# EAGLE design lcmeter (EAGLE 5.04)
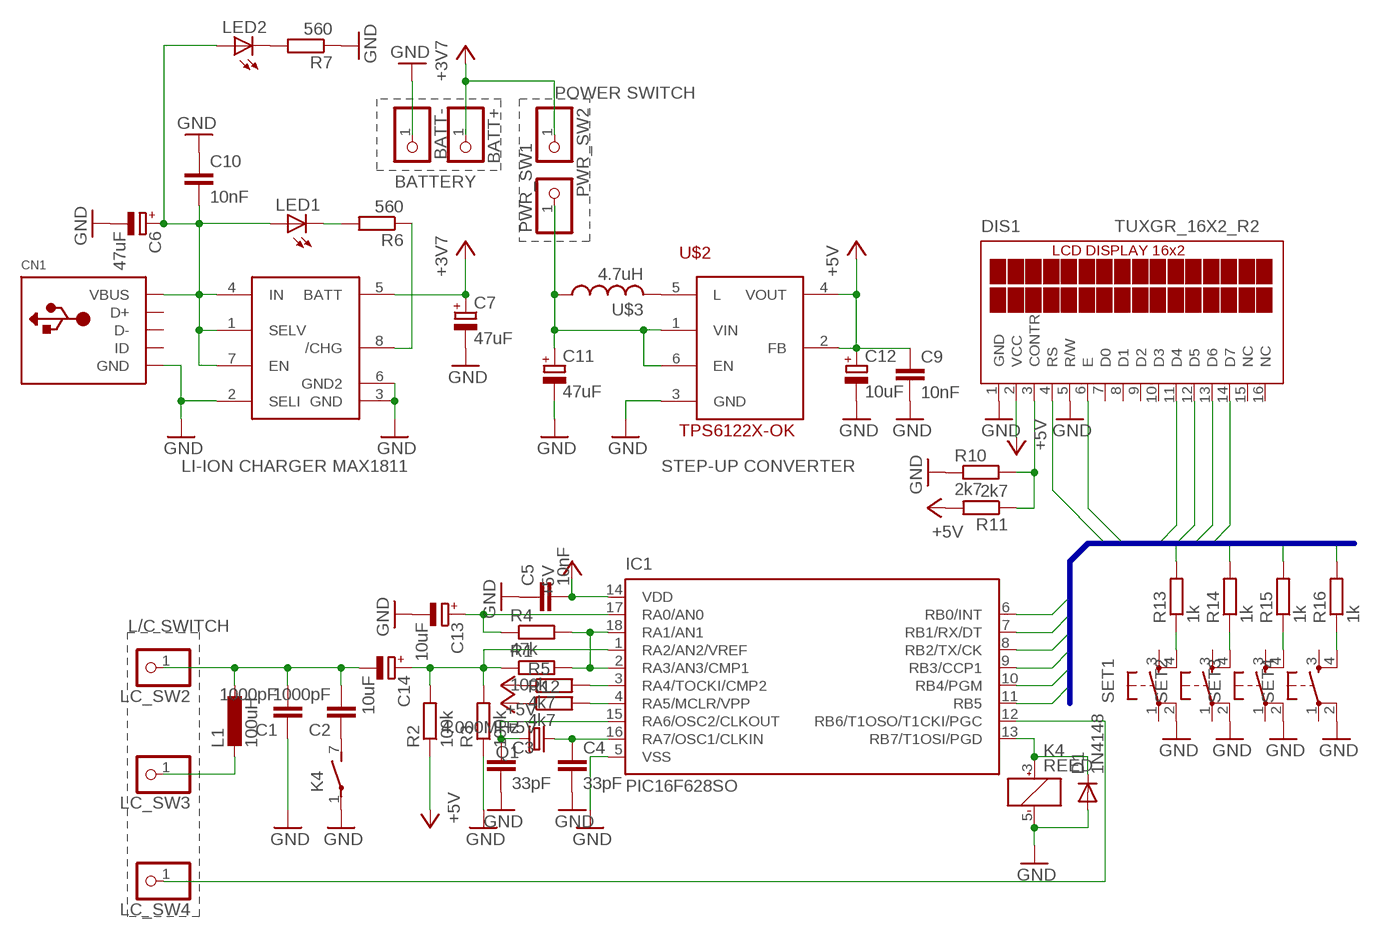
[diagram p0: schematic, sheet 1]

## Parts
BATT+  PINHD-1X1  [1X01]
BATT-  PINHD-1X1  [1X01]
C1  1000pF  C-EUC0805  [C0805]
C2  1000pF  C-EUC0805  [C0805]
C3  33pF  C-EUC0805  [C0805]
C4  33pF  C-EUC0805  [C0805]
C5  10nF  C-EUC0805  [C0805]
C6  47uF  CPOL-EUB/3528-21W  [B/3528-21W]
C7  47uF  CPOL-EUB/3528-21W  [B/3528-21W]
C9  10nF  C-EUC0805  [C0805]
C10  10nF  C-EUC0805  [C0805]
C11  47uF  CPOL-EUB/3528-21W  [B/3528-21W]
C12  10uF  CPOL-EUB/3528-21W  [B/3528-21W]
C13  10uF  CPOL-EUB/3528-21W  [B/3528-21W]
C14  10uF  CPOL-EUB/3528-21W  [B/3528-21W]
CN1  USBMINIB  [USB-MINIB]
D1  1N4148  DIODE-MINIMELF  [MINIMELF]
DIS1  TUXGR_16X2_R2  [TUXGR_16X2_R2]
IC1  PIC16F628SO  [SO-18W]
K4  REED  [REED]
L1  100uH  L-EU0204/5  [0204/5]
LC_SW2  PINHD-1X1  [1X01]
LC_SW3  PINHD-1X1  [1X01]
LC_SW4  PINHD-1X1  [1X01]
LED1  LED1206  [LED-1206]
LED2  LED1206  [LED-1206]
PWR_SW1  PINHD-1X1  [1X01]
PWR_SW2  PINHD-1X1  [1X01]
Q1  4.000MHz  CRYSTAL_CRYTALSM49  [CRYSTAL_SM49]
R1  100k  R-EU_R0603  [R0603]
R2  100k  R-EU_R0603  [R0603]
R3  100k  R-EU_R0603  [R0603]
R4  47k  R-EU_R0603  [R0603]
R5  4k7  R-EU_R0603  [R0603]
R6  560  R-EU_R0603  [R0603]
R7  560  R-EU_R0603  [R0603]
R10  2k7  R-EU_R0603  [R0603]
R11  2k7  R-EU_R0603  [R0603]
R12  4k7  R-EU_R0603  [R0603]
R13  1k  R-EU_R0603  [R0603]
R14  1k  R-EU_R0603  [R0603]
R15  1k  R-EU_R0603  [R0603]
R16  1k  R-EU_R0603  [R0603]
SET1  TAC_SWITCHPTH  [TACTILE-PTH]
SET2  TAC_SWITCHPTH  [TACTILE-PTH]
SET3  TAC_SWITCHPTH  [TACTILE-PTH]
SET4  TAC_SWITCHPTH  [TACTILE-PTH]
U$1  MAX1811SO8  [SO08]
U$2  TPS6122X-OK  [SC70-6]
U$3  4.7uH  EPL3015-OK  [EPL3015]

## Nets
+3V3: BATT+.1 C7.+ PWR_SW2.1 U$1.5(BATT) ; supply symbol labelled +3V7
+5V: C5.2 C9.1 C12.+ DIS1.2(VCC) IC1.14(VDD) R2.1 R5.1 R11.2 R12.1 U$2.2(FB) U$2.4(VOUT)
GND: BATT-.1 C1.1 C3.2 C4.2 C5.1 C6.- C7.- C9.2 C10.1 C11.- C12.- C13.- CN1.GND D1.A DIS1.1(GND) DIS1.5(R/W) IC1.5(VSS) K4.1(2:P) K4.5(1:-) R3.1 R7.1 R10.1 SET1.2 SET2.2 SET3.2 SET4.2 U$1.2(SELI) U$1.3(GND) U$1.6(GND2) U$2.3(GND)
LCDPIN0: DIS1.4(RS) IC1.6(RB0/INT)
LCDPIN1: DIS1.6(E) IC1.7(RB1/RX/DT)
LCDPIN2: DIS1.11(D4) IC1.8(RB2/TX/CK) R13.2
LCDPIN3: DIS1.12(D5) IC1.9(RB3/CCP1) R14.2
LCDPIN4: DIS1.13(D6) IC1.11(RB5) R15.2
LCDPIN5: DIS1.14(D7) IC1.10(RB4/PGM) R16.2
N$1: C13.+ IC1.17(RA0/AN0) R4.1
N$2: IC1.2(RA3/AN3/CMP1) IC1.18(RA1/AN1) R1.2 R4.2
N$3: C14.+ IC1.1(RA2/AN2/VREF) R1.1 R2.2 R3.2
N$4: C1.2 C2.2 C14.- L1.1 LC_SW2.1
N$5: DIS1.3(CONTR) R10.2 R11.1
N$6: C2.1 K4.7(2:S)
N$7: IC1.3(RA4/TOCKI/CMP2) R5.2
N$8: IC1.12(RB6/T1OSO/T1CKI/PGC) LC_SW4.1
N$9: C4.1 IC1.16(RA7/OSC1/CLKIN) Q1.1
N$10: C3.1 IC1.15(RA6/OSC2/CLKOUT) Q1.2
N$11: D1.C IC1.13(RB7/T1OSI/PGD) K4.3(1:+)
N$12: R13.1 SET1.4
N$13: R14.1 SET2.4
N$14: R15.1 SET3.4
N$15: R16.1 SET4.4
N$16: IC1.4(RA5/MCLR/VPP) R12.2
N$17: L1.2 LC_SW3.1
N$18: C6.+ C10.2 CN1.VBUS LED1.A LED2.A U$1.1(SELV) U$1.4(IN) U$1.7(EN)
N$19: U$2.5(L) U$3.P$2
N$20: LED1.C R6.2
N$21: R6.1 U$1.8(/CHG)
N$23: C11.+ PWR_SW1.1 U$2.1(VIN) U$2.6(EN) U$3.P$1
N$24: LED2.C R7.2
Unconnected: CN1.D+ CN1.D- CN1.ID DIS1.7(D0) DIS1.8(D1) DIS1.9(D2) DIS1.10(D3) DIS1.15(NC) DIS1.16(NC) SET1.1 SET1.3 SET2.1 SET2.3 SET3.1 SET3.3 SET4.1 SET4.3

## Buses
LCDPIN[0..5]

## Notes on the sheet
- POWER SWITCH
- BATTERY
- LI-ION CHARGER MAX1811 | STEP-UP CONVERTER
- L/C SWITCH

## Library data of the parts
BATT+ BATT- LC_SW2-LC_SW4 PWR_SW1 PWR_SW2 = adafruit:PINHD-1X1: Pin header 1x1 for 0.1" spacing
C1-C5 C9 C10 = rcl:C-EU: CAPACITOR, European symbol
C6 C7 C11-C14 = rcl:CPOL-EU: POLARIZED CAPACITOR, European symbol
CN1 = adafruit:USB: USB Connectors USBMINIB - Surface Mount Female Mini-B USB Connector 4UConnector: 06564 By microbuilder.eu Thru-hole RA Female Mini-B USB Connector 4UConnector: 18732 By ladyada.net
D1 = diode:DIODE-: DIODE
DIS1 = display-lcd:TUXGR_16X2_R2: Tuxgraphics LCD display 16x2 characters reflective, without background light Source: tuxgr_12x2_r2.pdf
IC1 = microchip:PIC16F62*: FLASH-Based 8-Bit CMOS Microcontroller Source: http://ww1.microchip.com/downloads/en/DeviceDoc/40300C.pdf
K4 = relay:REED: RELAY reed, 1 x norm. open with polarity, grid 5.08
L1 = rcl:L-EU: INDUCTOR, European symbol
LED1 LED2 = SparkFun:LED: LEDs
Q1 = icetubes:CRYSTAL_CRYTAL: CRYSTAL
R1-R7 R10-R16 = rcl:R-EU_: RESISTOR, European symbol
SET1-SET4 = SparkFun:TAC_SWITCH: Momentary Switch Button commonly used for reset or general input. Spark Fun Electronics SKU : COM-00097
U$1 = adafruit:MAX1811: Maxim MAX1811 USB li-ion battery charger http://www.ladyada.net/library/eagle
U$2 = trax_540:TPS6122X
U$3 = trax_540:EPL3015

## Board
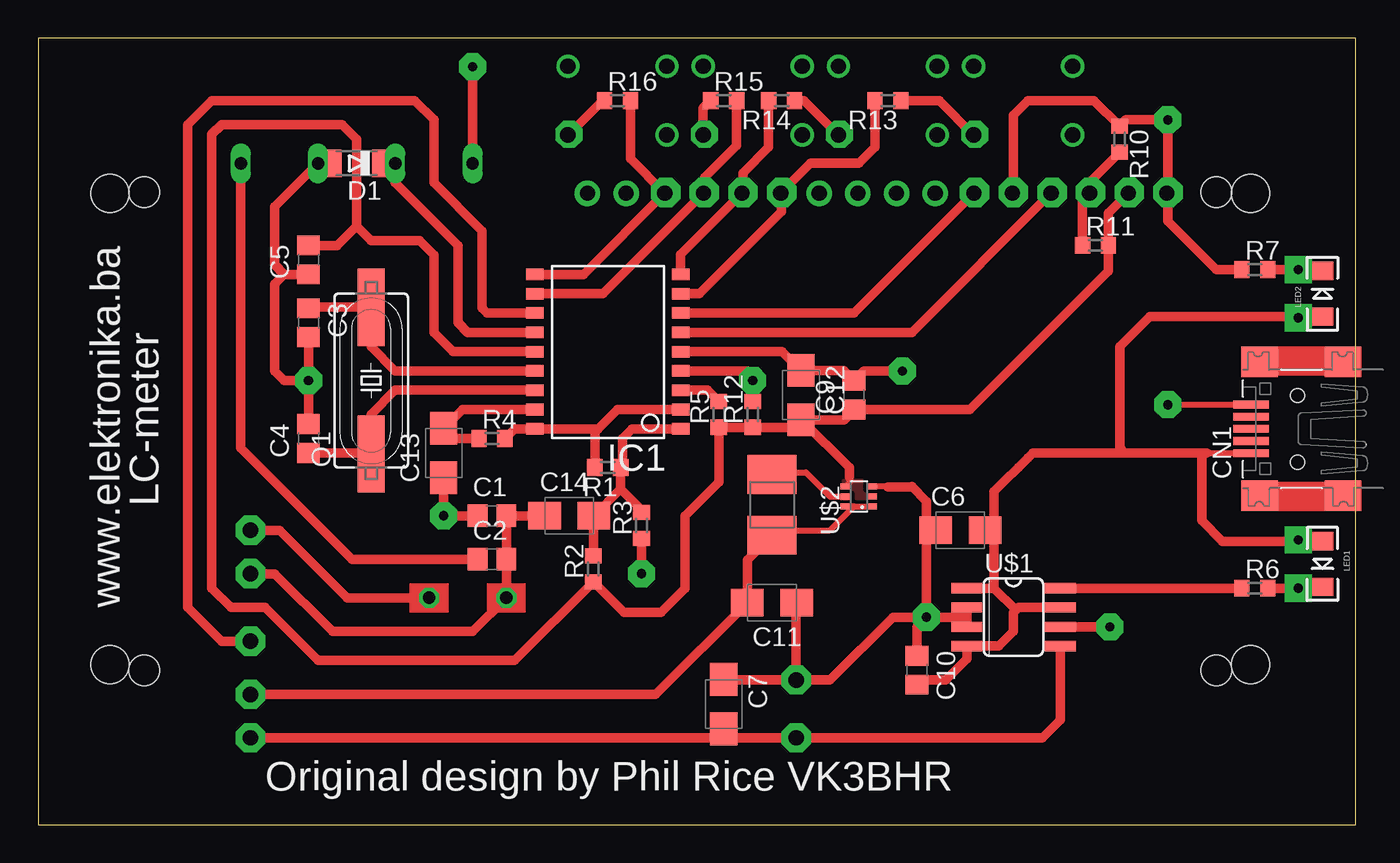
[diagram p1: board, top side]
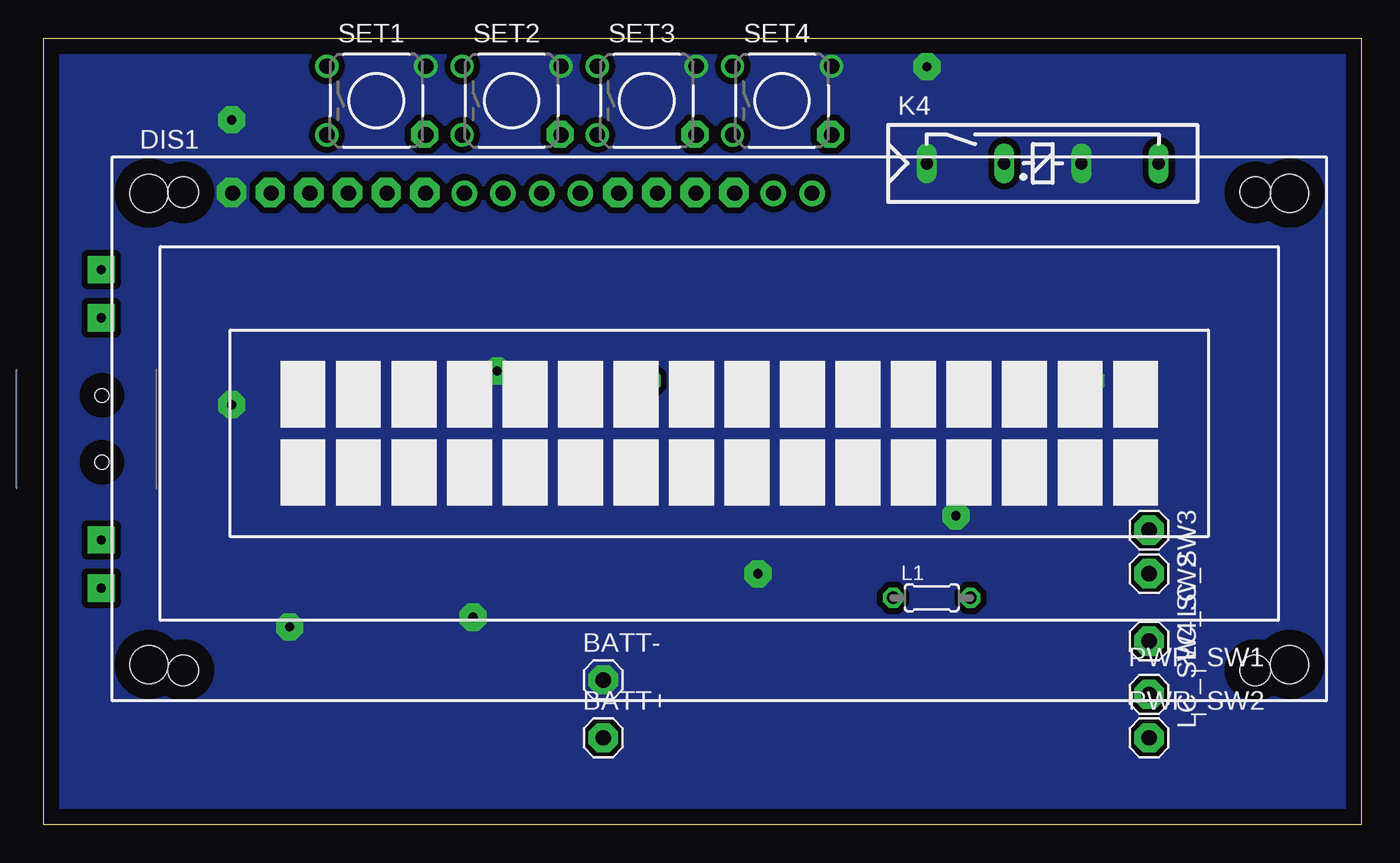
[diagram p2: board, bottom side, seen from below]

Size 86.66 x 51.74 mm. Coordinates in mm from the lower left corner, seen from the top.
Outline: 0,0 86.66,0 86.66,51.74 0,51.74 0,0
Copper layers (1*16): Top 0.035mm / dielectric 1.5mm / Bottom 0.035mm
Design rules "default": minimum track width 10mil, minimum drill 24mil, track to track 8mil, track to pad 8mil, pad to pad 8mil, via to via 8mil, smd to smd 8mil, copper to edge 40mil, drill to drill 8mil, minimum pad ring 10mil, minimum via ring 8mil, stop-mask expansion 4mil, vias tented up to drill 0mil, thermal gap 10mil
Holes 2 mm at 6.99,41.59 6.99,10.16 77.47,41.59 77.47,10.16

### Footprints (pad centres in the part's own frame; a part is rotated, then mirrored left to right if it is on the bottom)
1X01 = drill 1.016 pad 1.93 octagon: 1 0,0
C0805 = smd 1.3 x 1.5: 1 -0.95,0; 2 0.95,0
B/3528-21W = smd 2.15 x 1.8: + 1.625,0; - -1.625,0
USB-MINIB = smd 0.5 x 2.308: D+ 0,4.064; D- -0.8,4.064; GND 1.6,4.064; ID 0.8,4.064; VBUS -1.6,4.064 | smd 2 x 2.4: GND1 -4.4,-2; GND2 -4.4,3.5; GND3 4.4,3.5; GND4 4.4,-2 | hole 0.9: -2.2,1; 2.2,1
MINIMELF = smd 1.4 x 1.8: A 1.7,0; C -1.7,0
TUXGR_16X2_R2 = drill 1 pad 1.676 round: 1 -32,15.5; 2 -29.46,15.5; 3 -26.92,15.5; 4 -24.38,15.5; 5 -21.84,15.5; 6 -19.3,15.5; 7 -16.76,15.5; 8 -14.22,15.5; 9 -11.68,15.5; 10 -9.14,15.5; 11 -6.6,15.5; 12 -4.06,15.5; 13 -1.52,15.5; 14 1.02,15.5; 15 3.56,15.5; 16 6.1,15.5 | hole 2.5: -37.5,-15.5; 37.5,-15.5; -37.5,15.5; 37.5,15.5
SO-18W = smd 0.762 x 1.143: 1 -5.08,-4.788; 2 -3.81,-4.788; 3 -2.54,-4.788; 4 -1.27,-4.788; 5 0,-4.788; 6 1.27,-4.788; 7 2.54,-4.788; 8 3.81,-4.788; 9 5.08,-4.788; 10 5.08,4.788; 11 3.81,4.788; 12 2.54,4.788; 13 1.27,4.788; 14 0,4.788; 15 -1.27,4.788; 16 -2.54,4.788; 17 -3.81,4.788; 18 -5.08,4.788
REED = drill 0.813 long: 1 -17.78,2.54; 3 -12.7,2.54; 5 -7.62,2.54; 7 -2.54,2.54
0204/5 = drill 0.813 octagon: 1 -2.54,0; 2 2.54,0
LED-1206 = smd 1.2 x 1.4: A -1.5,0; C 1.5,0
CRYSTAL_SM49 = smd 5.08 x 1.778: 1 -4.826,0; 2 4.826,0
R0603 = smd 1 x 1.1: 1 -0.85,0; 2 0.85,0
TACTILE-PTH = drill 1.016 round: 1 -3.251,2.261; 2 3.251,2.261; 3 -3.251,-2.261; 4 3.251,-2.261
SO08 = smd 0.66 x 2.032: 1 -1.905,-3.073; 2 -0.635,-3.073; 3 0.635,-3.073; 4 1.905,-3.073; 5 1.905,3.073; 6 0.635,3.073; 7 -0.635,3.073; 8 -1.905,3.073
SC70-6 = smd 0.4 x 0.7: 1 -0.65,-0.85; 2 0,-0.85; 3 0.65,-0.85; 4 0.65,0.85; 5 -0.015,0.85; 6 -0.65,0.85
EPL3015 = smd 2.54 x 3.2: P$1 -0.953,0; P$2 3.035,0

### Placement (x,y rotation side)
BATT+  49.85,5.71 0 bottom
BATT-  49.85,9.53 0 bottom
C1  29.84,20.32 0 top
C2  29.84,17.46 0 top
C3  17.78,33.02 270 top
C4  17.78,25.4 90 top
C5  17.78,37.15 90 top
C6  60.64,19.37 0 top
C7  45.09,7.94 270 top
C9  53.66,28.26 90 top
C10  57.78,10.16 270 top
C11  48.26,14.61 180 top
C12  50.16,28.26 270 top
C13  26.67,24.45 90 top
C14  34.92,20.32 0 top
CN1  83.82,26.04 90 top
D1  20.95,43.5 180 top
DIS1  42.23,26.04 0 bottom
IC1  37.47,31.11 90 top
K4  10.79,40.96 0 bottom
L1  28.26,14.92 0 bottom
LC_SW2  13.97,16.51 270 bottom
LC_SW3  13.97,19.37 270 bottom
LC_SW4  13.97,12.06 270 bottom
LED1  84.45,17.14 270 top
LED2  84.45,34.92 90 top
PWR_SW1  13.97,8.57 0 bottom
PWR_SW2  13.97,5.71 0 bottom
Q1  21.91,29.21 90 top
R1  37.47,23.5 180 top
R2  36.51,16.83 90 top
R3  39.69,19.68 90 top
R4  29.84,25.4 0 top
R5  44.77,26.99 90 top
R6  80.01,15.56 0 top
R7  80.01,36.51 0 top
R10  71.12,45.09 270 top
R11  69.53,38.1 0 top
R12  46.99,26.99 90 top
R13  55.88,47.62 180 top
R14  48.9,47.62 180 top
R15  45.09,47.62 0 top
R16  38.1,47.62 0 top
SET1  64.77,47.62 0 bottom
SET2  55.88,47.62 0 bottom
SET3  46.99,47.62 0 bottom
SET4  38.1,47.62 0 bottom
U$1  64.14,13.65 270 top
U$2  53.98,21.59 90 top
U$3  48.26,20 90 top

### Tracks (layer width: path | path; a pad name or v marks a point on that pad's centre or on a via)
+3V3
  Top 0.61: PWR_SW2.1 45.09,5.71 | 45.09,5.71 BATT+.1 66.04,5.71 67.21,6.88 U$1.5 | 45.09,5.71 C7.+
+5V
  Top 0.406: 53.34,22.86 53.34,22.45 U$2.4
  Top 0.61: IC1.14 27.3,31.11 26.04,32.38 26.04,37.47 25.08,38.42 21.91,38.42 20.95,39.37 | 20.95,39.37 20.95,45.09 20,46.04 12.06,46.04 11.43,45.4 11.43,15.56 12.7,14.29 14.92,14.29 18.41,10.79 31.33,10.79 R2.1 38.52,13.97 40.96,13.97 42.55,15.56 42.55,20.32 44.77,22.54 R5.1 R12.1 49.67,26.14 C12.+ | 20.95,39.37 19.68,38.1 C5.2 | C12.+ 50.2,26.63 53.34,23.5 53.34,22.86 | C12.+ 52.98,26.63 C9.1 61.28,27.3 70.38,36.41 R11.2 70.38,40.23 DIS1.2
  pour Top (isolate 0.229, no thermals): 53.02,22.54 53.02,21.27 54.93,21.27 54.93,22.54
GND  (via drill 0.6 pad 1.78, 0.6 pad 1.93)
  Top 0.406: CN1.GND 74.31,27.64 v74.3,27.62 | U$2.3 55.87,22.24 arc-90 55.88,22.23
  Top 0.61: v74.3,41.59 v74.3,46.35 71.54,46.35 R10.1 69.43,47.62 65.09,47.62 64.14,46.67 64.14,41.6 DIS1.5 | 61.06,13.65 U$1.3 | 61.06,13.65 U$1.2 | U$1.6 v70.48,13.02 | v58.42,13.65 61.06,13.65 | C10.1 57.78,13.02 v58.42,13.65 | C4.2 v17.78,29.21 | v17.78,29.21 C3.2 | D1.A K4.5 15.56,40.64 15.56,36.83 16.19,36.2 | C5.1 16.2,36.2 16.19,36.2 | 16.19,36.2 15.56,35.56 15.56,29.84 16.19,29.21 v17.78,29.21 | K4.1 v28.57,49.85 | C13.- v26.67,20.32 C1.1 | v39.69,16.51 R3.1 | IC1.5 48.93,31.11 C12.- 52.98,29.88 C9.2 54.3,29.84 v56.83,29.84 | C11.- 49.85,14.57 BATT-.1 | BATT-.1 52.07,9.53 56.2,13.65 v58.42,13.65 | v58.42,13.65 58.42,19.37 | 58.42,19.37 58.42,21.27 57.45,22.24 57.45,22.23 55.88,22.23 | R7.1 77.47,36.51 74.3,39.69 74.3,41.47 DIS1.1 | BATT-.1 45.12,9.53 C7.- | 58.42,19.37 C6.-
  pour Bottom (isolate 0.406, no thermals): -0.64,52.39 87.31,52.39 87.31,-0.64 -0.64,-0.64
LCDPIN0
  Top 0.61: IC1.6 57.46,32.38 DIS1.4
LCDPIN1
  Top 0.61: IC1.7 53.65,33.66 DIS1.6
LCDPIN2
  Top 0.61: R13.2 55.03,44.55 53.98,43.5 50.79,43.5 DIS1.11 48.9,41.47 48.9,40.32 43.5,34.92 IC1.8
LCDPIN3
  Top 0.61: R14.2 48.05,44.55 46.35,42.86 46.35,41.6 DIS1.12 42.25,37.5 IC1.9
LCDPIN4
  Top 0.61: R15.2 45.94,44.66 43.81,42.55 43.81,41.6 DIS1.13 37.14,34.92 IC1.11
LCDPIN5
  Top 0.61: R16.2 38.95,43.79 DIS1.14 35.87,36.2 IC1.10
N$1
  Top 0.61: IC1.17 27.9,27.3 C13.+ 27.34,25.4 R4.1
N$2
  Top 0.61: IC1.2 38.1,27.3 36.83,26.04 36.51,26.04 | 36.51,26.04 IC1.18 31.33,26.04 R4.2 | R1.2 36.62,25.93 36.51,26.04
N$3
  Top 0.61: IC1.1 39.05,26.04 38.42,25.4 38.42,23.6 R1.1 38.31,22.09 | 38.31,22.09 C14.+ 36.51,20.28 R2.2 | R3.2 39.69,20.71 38.31,22.09
N$4
  Top 0.61: 33.02,20.04 C14.- C1.2 C2.2 L1.1 28.57,12.7 19.37,12.7 15.56,16.51 LC_SW2.1
N$5
  Top 0.61: 68.58,38 R11.1 68.68,41.07 DIS1.3 69.15,42.26 R10.2
N$6
  Top 0.61: C2.1 20.64,17.46 13.34,24.77 K4.7
N$7
  Top 0.61: IC1.3 44.03,28.57 R5.2
N$8
  Top 0.61: IC1.12 29.53,33.66 29.21,33.97 29.21,39.05 26.04,42.23 26.04,46.35 24.77,47.62 11.43,47.62 9.84,46.04 9.84,14.29 12.06,12.06 LC_SW4.1
N$9
  Top 0.61: Q1.1 21.34,23.82 | IC1.16 23.5,28.57 21.91,26.99 Q1.1 | C4.1 21.84,24.45 Q1.1
N$10
  Top 0.61: IC1.15 23.5,29.84 21.91,31.43 Q1.2 17.85,34.04 C3.1
N$11
  Top 0.61: D1.C K4.3 23.5,42.23 27.62,38.1 27.62,33.02 28.26,32.38 IC1.13
N$12
  Top 0.61: R13.1 59.26,47.62 SET1.4
N$13
  Top 0.61: R14.1 50.37,47.62 SET2.4
N$14
  Top 0.61: R15.1 43.74,47.13 SET3.4
N$15
  Top 0.61: R16.1 37.11,47.62 SET4.4
N$16  (via drill 0.6 pad 1.78)
  Top 0.61: IC1.4 46.67,29.84 46.99,29.53 v46.99,29.21 R12.2
N$17
  Top 0.61: L1.2 20.32,14.92 15.88,19.37 LC_SW3.1
N$18
  Top 0.406: CN1.VBUS 79.43,24.45 76.83,24.45
  Top 0.61: 64.29,14.13 64.14,13.97 64.14,12.7 63.18,11.75 U$1.4 61.06,10.9 59.69,9.53 58.1,9.53 C10.2 | 64.29,14.13 64.45,14.29 U$1.7 | 62.87,15.56 U$1.1 | 64.29,14.13 62.87,15.56 | 71.44,24.45 65.41,24.45 65.09,24.13 | 71.44,24.45 76.52,24.45 | 76.52,24.45 76.83,24.45 | 65.09,24.13 64.45,23.5 | 62.87,15.56 62.87,19.37 | 62.87,19.37 62.87,21.91 65.09,24.13 | LED1.A 77.88,18.64 76.52,20 76.52,24.45 | LED2.A 73.11,33.42 71.12,31.43 71.12,24.77 71.44,24.45 | 62.87,19.37 C6.+
N$19
  Top 0.406: U$2.5 52.09,21.57 50.48,23.18 48.4,23.18 U$3.P$2
N$20  (via drill 0.6 pad 1.78)
  Top 0.61: R6.2 v82.87,15.56 84.37,15.56 LED1.C
N$21
  Top 0.61: U$1.8 R6.1
N$22  (via drill 0.6 pad 1.78)
  other vias: 34.92,45.4
N$23
  Top 0.406: 53.66,20.94 U$2.6 | 53.66,20.94 U$2.1 | U$3.P$1 48.58,19.37 52.09,19.37 53.66,20.94
  Top 0.61: U$3.P$1 46.63,17.43 C11.+ 40.6,8.57 PWR_SW1.1
N$24  (via drill 0.6 pad 1.78)
  Top 0.61: R7.2 v82.87,36.51 84.37,36.51 LED2.C
N$25  (via drill 0.6 pad 1.78)
  other vias: 43.81,45.4
N$26  (via drill 0.6 pad 1.78)
  other vias: 52.7,45.4
N$27  (via drill 0.6 pad 1.78)
  other vias: 61.59,45.4
N$28  (via drill 0.6 pad 1.93)
  other vias: 41.27,41.59
N$29  (via drill 0.6 pad 1.93)
  other vias: 43.81,41.59
N$30  (via drill 0.6 pad 1.93)
  other vias: 46.35,41.59
N$31  (via drill 0.6 pad 1.93)
  other vias: 48.9,41.59
N$32  (via drill 0.6 pad 1.93)
  other vias: 61.59,41.59
N$33  (via drill 0.6 pad 1.93)
  other vias: 64.14,41.59
N$34  (via drill 0.6 pad 1.93)
  other vias: 66.67,41.59
N$35  (via drill 0.6 pad 1.93)
  other vias: 69.22,41.59
N$36  (via drill 0.6 pad 1.93)
  other vias: 71.75,41.59
N$37  (via drill 0.6 pad 1.78)
  other vias: 82.87,33.34
N$38  (via drill 0.6 pad 1.78)
  other vias: 82.87,18.73
(copper drawn outside any net)
  shapes: Top area x4

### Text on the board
_tsilk: LC-meter | www.elektronika.ba | Original design by Phil Rice VK3BHR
